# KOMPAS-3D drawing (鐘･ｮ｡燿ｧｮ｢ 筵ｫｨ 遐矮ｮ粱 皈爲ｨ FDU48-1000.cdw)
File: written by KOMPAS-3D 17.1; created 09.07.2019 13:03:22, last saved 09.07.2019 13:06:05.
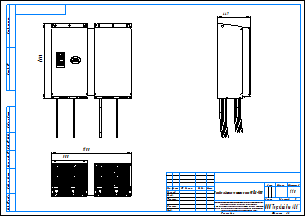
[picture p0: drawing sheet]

Sheet 1: A3, landscape

Title block, sheet 1: name: Преобразователи частоты серии FDU48-1000; sheets: 1; sheet format: A3; stored path: \\adlc.lan\data\АДЛ_ПКД\3D-модели\Поставщики\Оборудование Emotron\Преобразователи частоты\Серия FDU 2.0\KOMPAS 2D\Преобразователи частоты серии FDU48-1000.cdw

Views: Вид 1
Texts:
  user
  CONTINUOUS_RGB_0_0_0_THICK_0.18
  POLYLINE_STYLE_0.18_RGB_0_0_0
  Рама для чертежей
  Лит-Масса-Масштаб
  Материал-Предприятие
  Масштаб
  Изм.
  Лист
  № докум.
  Подп.
  Дата
  Лит.
  Разраб.
  Пров.
  Т.контр.
  Листов
  Внимание! Данный продукт является объектом авторского права ООО «Торговый Дом АДЛ».
  Запрещается изменение, копирование, распространение
  (в том числе путем копирования на другие сайты и ресурсы в Интернете)
  или любое иное использование информации и объектов без предварительного
  согласия правообладателя (ООО «Торговый Дом АДЛ»).
  Н.контр.
  Утв.
  ООО "Торговый дом АДЛ"
  Изменение
  Номер документа
  Подпись
  Обозначение документа
  Наименование изделия
  Масса изделия по ГОСТ 2.109-73
  Порядковый номер листа
  Общее количество листов в документе
  Характер работы, выполненной лицом, подписавшим документ
  Наименование или индекс предприятия, выпускающего документ
  Инв. № подл.
  Подп. и дата
  Взам. инв. №
  Инв. № дубл.
  Инвентарный номер подлинника по ГОСТ 2.501-68
  Подпись принявшего подлинник в отдел технической документации
  Инвентарный номер подлинника, взамен которого выпущен данный подлинник
  Инвентарный номер дубликата по ГОСТ 2.502-68
  Подпись принявшего дубликат в отдел технической документации
  Справ. №
  Перв. примен.
  Обозначение документа, взамен или на основании которого выпущен данный документ
  Обозначение документа, в котором впервые записан данный документ
  Подпись лица, копировавшего чертеж
  Обозначение формата листа
  !Рама для чертежа
Dimensions and other numbers on the sheet: 1100; 500; 1036; 449; 1:10; 1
